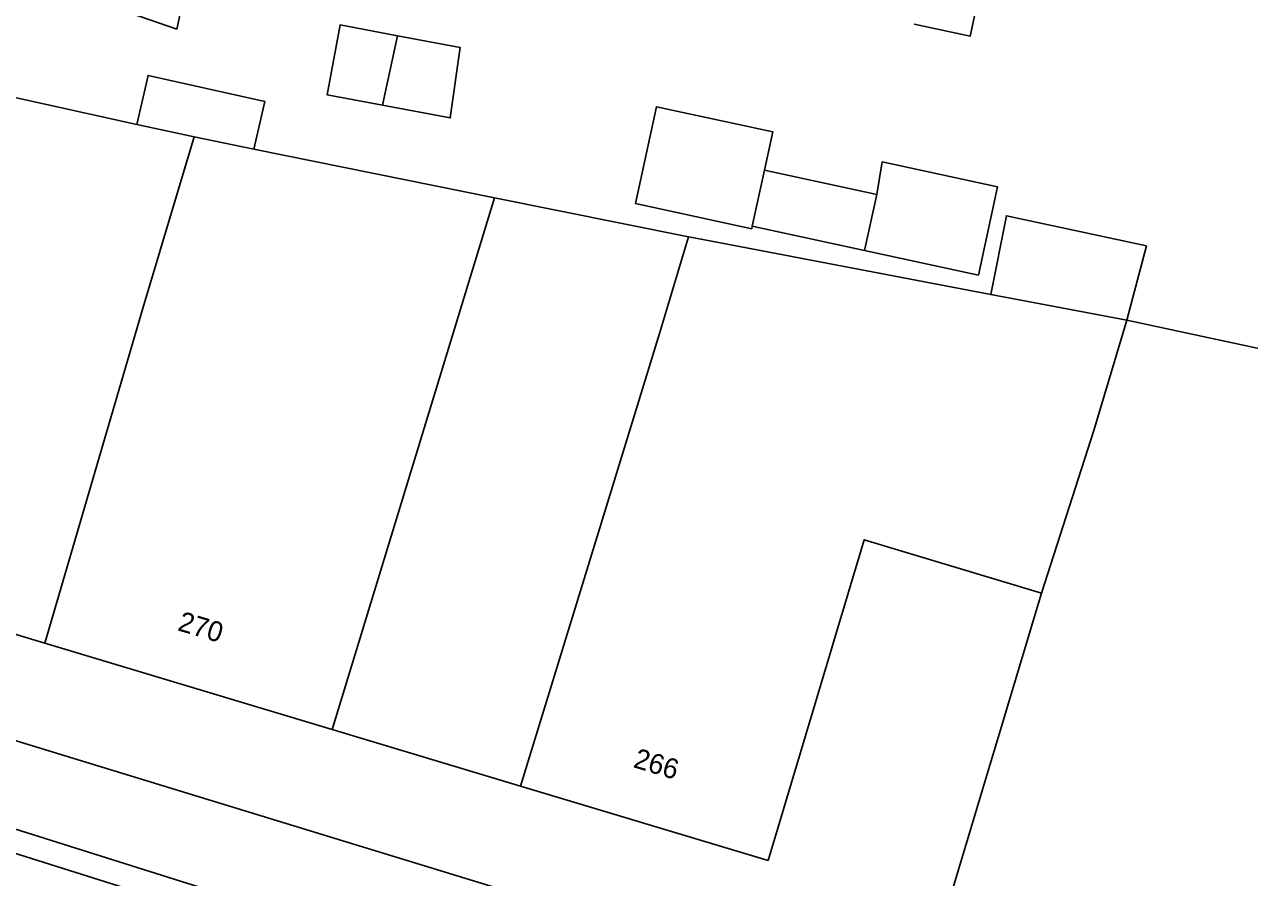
# Model space of a CAD drawing. Extents: x 158087 to 159494, y 382905 to 383981.
# Drawn here: x 158217.7 to 158278.9, y 383127.9 to 383170.5 of the extents above; entities that cross this region are included whole.
import ezdxf

# ---------------------------------------------------------------- set-up
doc = ezdxf.new("R2010")
doc.units = 0
for name, color, linetype in [('IMGEO_Erf', 7, 'Continuous'), ('IMGEO_Pand', 7, 'Continuous'), ('IMGEO_Pand_nummerreeks', 7, 'Continuous'), ('IMGEO_Rijbaan_lokaal_gesloten', 7, 'Continuous'), ('IMGEO_Voetpad_open', 7, 'Continuous')]:
    doc.layers.add(name, color=color, linetype=linetype)

msp = doc.modelspace()

# ---------------------------------------------------------------- linework, layer by layer
at = {"layer": 'IMGEO_Erf'}
for points in [[(158241.194, 383161.869), (158250.887, 383159.916)], [(158233.074, 383135.301), (158242.482, 383132.476)]]:
    msp.add_lwpolyline(points, dxfattribs=at)
at = {"layer": 'IMGEO_Pand'}
for points in [[(158270.874, 383182.878), (158269.814, 383177.992), (158269.155, 383174.953), (158269.106, 383174.717), (158266.14, 383175.36), (158264.964, 383169.936), (158262.164, 383170.543)], [(158225.298, 383170.285), (158221.633, 383171.548), (158222.249, 383174.343), (158226.01, 383173.513), (158225.298, 383170.285)], [(158235.587, 383166.494), (158232.815, 383167.014), (158233.468, 383170.499), (158236.339, 383169.961)], [(158236.339, 383169.961), (158239.468, 383169.374), (158238.976, 383165.858), (158235.587, 383166.494)], [(158235.587, 383166.494), (158236.339, 383169.961)], [(158211.693, 383167.819), (158211.773, 383168.079), (158223.312, 383165.533)], [(158223.312, 383165.533), (158223.867, 383167.976), (158229.706, 383166.669), (158229.153, 383164.3)], [(158254.075, 383160.451), (158254.046, 383160.316), (158248.231, 383161.577), (158249.281, 383166.416), (158255.095, 383165.155), (158254.682, 383163.248)], [(158223.312, 383165.533), (158226.171, 383164.902)], [(158226.171, 383164.902), (158223.618, 383156.398), (158218.706, 383139.615)], [(158226.171, 383164.902), (158229.153, 383164.3)], [(158229.153, 383164.3), (158241.194, 383161.869)], [(158260.297, 383162.03), (158260.573, 383163.656), (158266.337, 383162.405), (158265.381, 383157.999), (158259.69, 383159.233)], [(158254.682, 383163.248), (158254.075, 383160.451)], [(158254.682, 383163.248), (158260.297, 383162.03)], [(158241.194, 383161.869), (158233.074, 383135.301)], [(158259.69, 383159.233), (158260.297, 383162.03)], [(158265.996, 383157.037), (158266.78, 383160.97), (158273.78, 383159.462), (158272.796, 383155.743)], [(158259.69, 383159.233), (158254.075, 383160.451)], [(158242.482, 383132.476), (158249.437, 383155.086), (158250.887, 383159.916)], [(158250.887, 383159.916), (158251.254, 383159.842), (158265.996, 383157.037)], [(158272.796, 383155.743), (158265.996, 383157.037)], [(158268.534, 383142.116), (158271.142, 383150.234), (158272.796, 383155.743)], [(158272.796, 383155.743), (158292.196, 383151.584)], [(158242.482, 383132.476), (158254.863, 383128.759), (158259.672, 383144.777), (158268.534, 383142.116)], [(158204.461, 383143.892), (158218.706, 383139.615)], [(158268.534, 383142.116), (158263.755, 383126.193), (158283.733, 383120.195)], [(158218.706, 383139.615), (158233.074, 383135.301)]]:
    msp.add_lwpolyline(points, dxfattribs=at)
at = {"layer": 'IMGEO_Rijbaan_lokaal_gesloten'}
for points in [[(158123.906, 383159.769), (158125.403, 383159.303), (158130.311, 383157.752), (158203.27, 383134.722), (158233.202, 383125.294), (158245.445, 383121.671), (158283.564, 383110.711), (158294.412, 383107.708)], [(158294.047, 383106.593), (158274.356, 383112.076), (158235.952, 383123.218), (158123.545, 383158.624)]]:
    msp.add_lwpolyline(points, dxfattribs=at)
at = {"layer": 'IMGEO_Voetpad_open'}
msp.add_lwpolyline([(158186.594, 383144.316), (158217.278, 383134.734), (158240.948, 383127.491), (158262.253, 383121.192), (158268.93, 383119.281)], dxfattribs=at)

# ---------------------------------------------------------------- texts
at = {"layer": 'IMGEO_Pand_nummerreeks'}
for s, p in [('270', (158225.298, 383140.267)), ('266', (158248.077, 383133.428))]:
    msp.add_text(s, height=1, rotation=343.28682, dxfattribs=at).set_placement(p)

doc.saveas('drawing.dxf')
